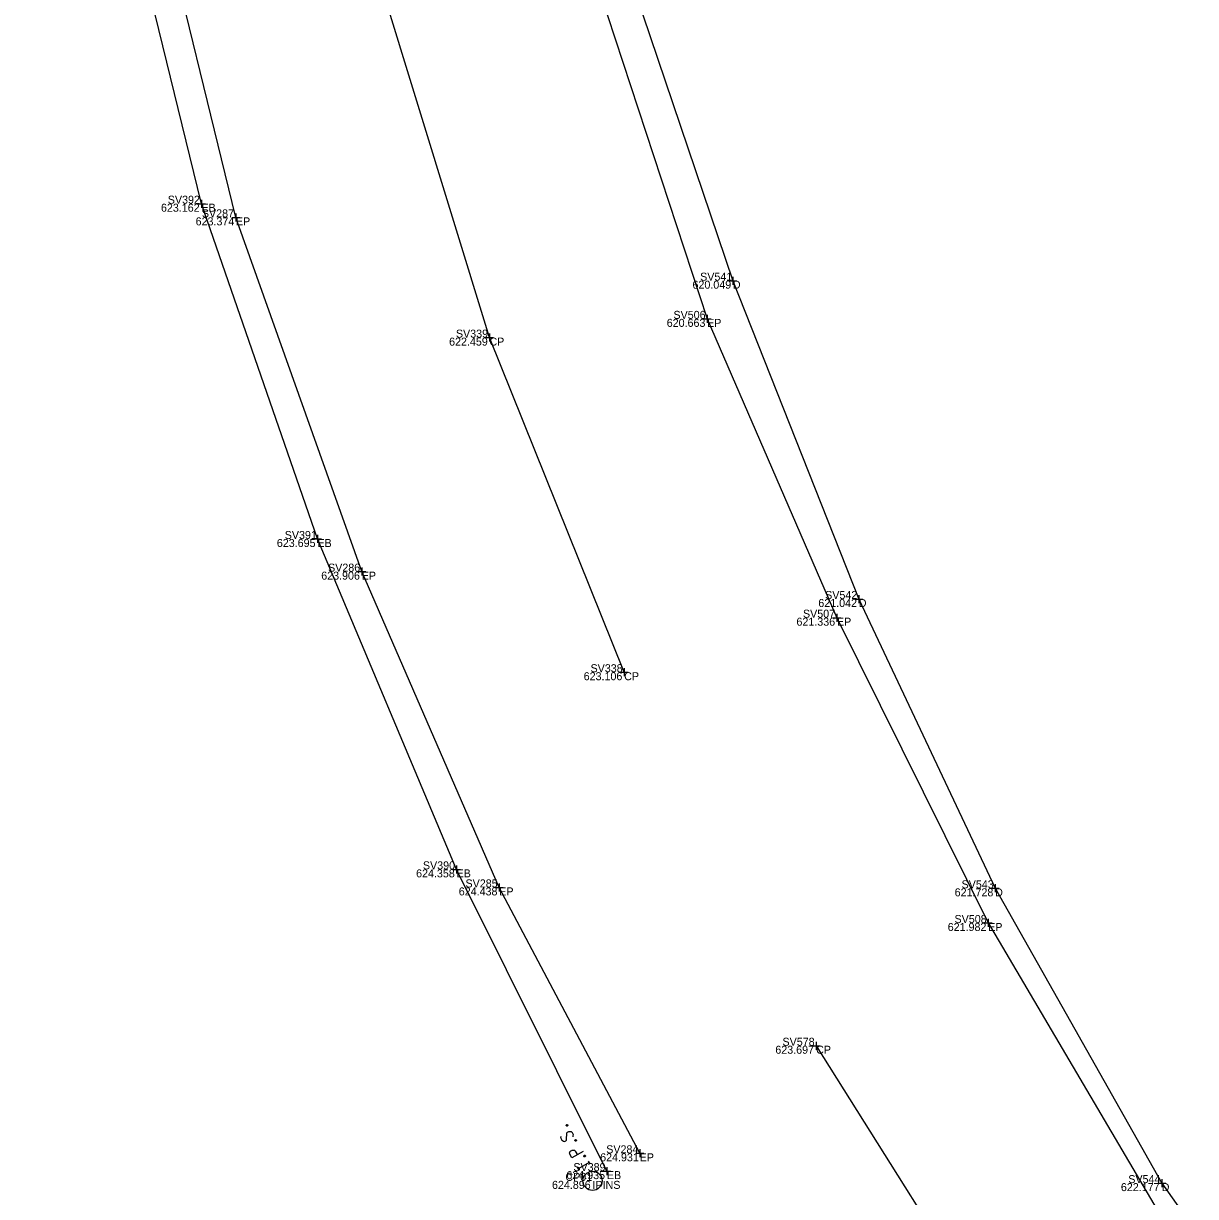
# Model space of a CAD drawing. Extents: x -2 to 1979875, y -2 to 232027.
# Drawn here: x 1978733.8 to 1978807.1, y 230654.1 to 230727.4 of the extents above; entities that cross this region are included whole.
import ezdxf

# ---------------------------------------------------------------- set-up
doc = ezdxf.new("R2010")
doc.units = 0
for name, color, linetype in [('_CIVIL_CONSTRUCTION', 7, 'Continuous'), ('DR_X_Ditch', 7, 'Continuous'), ('GE_X_Alignment', 7, 'Continuous'), ('GE_X_Alignment_1000_Curve_Data', 7, 'Continuous'), ('GE_X_Alignment_1000_Stations', 7, 'Continuous'), ('GE_X_Alignment_100_Curve_Data', 7, 'Continuous'), ('GE_X_Alignment_100_Stations', 7, 'Continuous'), ('RW_X_CL', 7, 'Continuous'), ('SC_Scratch1', 7, 'Continuous')]:
    doc.layers.add(name, color=color, linetype=linetype)

msp = doc.modelspace()

# ---------------------------------------------------------------- linework, layer by layer
at = {"layer": 'DR_X_Ditch'}
msp.add_lwpolyline([(1978771.125, 230732.191), (1978778.159, 230711.366), (1978786.031, 230691.476), (1978794.555, 230673.399), (1978804.965, 230654.98), (1978815.554, 230639.968), (1978828.294, 230624.497), (1978844.456, 230606.581), (1978859.572, 230591.097), (1978875.392, 230576.708), (1978886.516, 230567.847)], dxfattribs=at)
at = {"layer": 'GE_X_Alignment_1000_Curve_Data'}
for points in [[(1978771.368, 230686.901), (1978762.945, 230707.808), (1978756.184, 230729.845), (1978751.49, 230752.309), (1978748.994, 230772.916), (1978748.08, 230796.049), (1978747.937, 230796.247), (1978748.471, 230819.071), (1978749.254, 230839.296), (1978750.532, 230861.092), (1978751.977, 230883.907), (1978753.538, 230907.259), (1978755.272, 230931.005), (1978756.708, 230952.708), (1978758.182, 230974.871), (1978759.598, 230998.872), (1978761.121, 231023.464)], [(1978783.367, 230663.563), (1978795.266, 230644.644), (1978809.509, 230625.195), (1978825.084, 230606.888), (1978841.992, 230589.345), (1978859.09, 230573.66), (1978877.78, 230558.412), (1978896.865, 230543.975), (1978915.415, 230530.323), (1978933.509, 230517.252), (1978955.215, 230501.713), (1978975.371, 230487.136), (1978995.733, 230472.378), (1979015.234, 230458.051), (1979036.078, 230442.897)]]:
    msp.add_lwpolyline(points, dxfattribs=at)
at = {"layer": 'GE_X_Alignment_1000_Stations'}
for points in [[(1978772.336, 230656.843), (1978763.559, 230673.456), (1978754.964, 230693.186), (1978747.098, 230715.323), (1978742.189, 230735.369), (1978738.656, 230754.308), (1978736.533, 230775.816), (1978735.988, 230798.596), (1978736.151, 230819.454), (1978737.13, 230840.16), (1978738.357, 230863.144), (1978739.649, 230887.098), (1978741.331, 230908.702), (1978742.827, 230930.869), (1978744.275, 230952.773), (1978745.794, 230976.041), (1978747.11, 230998.611), (1978748.464, 231019.612), (1978749.988, 231043.472)], [(1978769.847, 230729.415), (1978776.553, 230708.98), (1978784.668, 230690.309), (1978794.119, 230671.233), (1978804.682, 230653.303), (1978817.78, 230635.658), (1978827.58, 230622.57), (1978841.659, 230607.55), (1978855.429, 230592.978), (1978873.114, 230576.871), (1978893.268, 230560.833), (1978915.513, 230544.403), (1978933.587, 230531.196), (1978953.659, 230517.09), (1978973.227, 230503.602), (1978990.133, 230491.392), (1979010.591, 230476.223), (1979030.079, 230461.641), (1979044.057, 230451.677)]]:
    msp.add_lwpolyline(points, dxfattribs=at)
at = {"layer": 'GE_X_Alignment_100_Curve_Data'}
for p, q in [((1978744.942, 230716.425), (1978744.942, 230715.925)), ((1978744.692, 230716.175), (1978745.192, 230716.175)), ((1978744.942, 230716.175), (1978744.942, 230716.175)), ((1978747.098, 230715.573), (1978747.098, 230715.073)), ((1978746.848, 230715.323), (1978747.348, 230715.323)), ((1978747.098, 230715.323), (1978747.098, 230715.323)), ((1978777.909, 230711.366), (1978778.409, 230711.366)), ((1978778.159, 230711.616), (1978778.159, 230711.116)), ((1978778.159, 230711.366), (1978778.159, 230711.366)), ((1978776.303, 230708.98), (1978776.803, 230708.98)), ((1978776.553, 230709.23), (1978776.553, 230708.73)), ((1978776.553, 230708.98), (1978776.553, 230708.98)), ((1978762.695, 230707.808), (1978763.195, 230707.808)), ((1978762.945, 230708.058), (1978762.945, 230707.558)), ((1978762.945, 230707.808), (1978762.945, 230707.808)), ((1978751.943, 230695.227), (1978752.443, 230695.227)), ((1978752.193, 230695.477), (1978752.193, 230694.977)), ((1978752.193, 230695.227), (1978752.193, 230695.227)), ((1978754.714, 230693.186), (1978755.214, 230693.186)), ((1978754.964, 230693.436), (1978754.964, 230692.936)), ((1978754.964, 230693.186), (1978754.964, 230693.186)), ((1978785.781, 230691.476), (1978786.281, 230691.476)), ((1978786.031, 230691.726), (1978786.031, 230691.226)), ((1978786.031, 230691.476), (1978786.031, 230691.476)), ((1978784.418, 230690.309), (1978784.918, 230690.309)), ((1978784.668, 230690.559), (1978784.668, 230690.059)), ((1978784.668, 230690.309), (1978784.668, 230690.309)), ((1978771.368, 230687.151), (1978771.368, 230686.651)), ((1978771.118, 230686.901), (1978771.618, 230686.901)), ((1978771.368, 230686.901), (1978771.368, 230686.901)), ((1978760.641, 230674.584), (1978761.141, 230674.584)), ((1978760.891, 230674.834), (1978760.891, 230674.334)), ((1978760.891, 230674.584), (1978760.891, 230674.584)), ((1978763.309, 230673.456), (1978763.809, 230673.456)), ((1978763.559, 230673.706), (1978763.559, 230673.206)), ((1978763.559, 230673.456), (1978763.559, 230673.456)), ((1978794.305, 230673.399), (1978794.805, 230673.399)), ((1978794.555, 230673.649), (1978794.555, 230673.149)), ((1978794.555, 230673.399), (1978794.555, 230673.399)), ((1978793.869, 230671.233), (1978794.369, 230671.233)), ((1978794.119, 230671.483), (1978794.119, 230670.983)), ((1978794.119, 230671.233), (1978794.119, 230671.233)), ((1978783.117, 230663.563), (1978783.617, 230663.563)), ((1978783.367, 230663.813), (1978783.367, 230663.313)), ((1978783.367, 230663.563), (1978783.367, 230663.563)), ((1978772.336, 230657.093), (1978772.336, 230656.593)), ((1978772.086, 230656.843), (1978772.586, 230656.843)), ((1978772.336, 230656.843), (1978772.336, 230656.843)), ((1978770.038, 230655.73), (1978770.538, 230655.73)), ((1978770.288, 230655.98), (1978770.288, 230655.48)), ((1978770.288, 230655.73), (1978770.288, 230655.73)), ((1978804.715, 230654.98), (1978805.215, 230654.98)), ((1978804.965, 230655.23), (1978804.965, 230654.73)), ((1978804.965, 230654.98), (1978804.965, 230654.98))]:
    msp.add_line(p, q, dxfattribs=at)
at = {"layer": 'RW_X_CL'}
for points in [[(1978767.754, 230658.556), (1978767.74, 230658.58), (1978767.743, 230658.601), (1978767.756, 230658.627), (1978767.784, 230658.643), (1978767.814, 230658.641), (1978767.833, 230658.633), (1978767.847, 230658.609), (1978767.844, 230658.589), (1978767.83, 230658.562), (1978767.803, 230658.546), (1978767.773, 230658.548), (1978767.754, 230658.556)], [(1978767.405, 230657.886), (1978767.399, 230657.87), (1978767.397, 230657.849), (1978767.405, 230657.797), (1978767.424, 230657.738), (1978767.446, 230657.7), (1978767.454, 230657.685), (1978767.507, 230657.633), (1978767.569, 230657.599), (1978767.632, 230657.59), (1978767.682, 230657.606), (1978767.714, 230657.625), (1978767.753, 230657.659), (1978767.769, 230657.72), (1978767.782, 230658.077), (1978767.79, 230658.113), (1978767.806, 230658.135), (1978767.834, 230658.163), (1978767.866, 230658.182), (1978767.902, 230658.196), (1978767.927, 230658.204), (1978767.959, 230658.21), (1978767.987, 230658.213), (1978768.009, 230658.213), (1978768.033, 230658.208), (1978768.052, 230658.2), (1978768.074, 230658.187), (1978768.088, 230658.176), (1978768.118, 230658.136), (1978768.157, 230658.069), (1978768.17, 230658.02), (1978768.168, 230657.936), (1978768.157, 230657.879)], [(1978768.297, 230657.61), (1978768.283, 230657.633), (1978768.286, 230657.654), (1978768.299, 230657.681), (1978768.327, 230657.697), (1978768.357, 230657.695), (1978768.376, 230657.687), (1978768.39, 230657.663), (1978768.387, 230657.642), (1978768.373, 230657.615), (1978768.346, 230657.6), (1978768.316, 230657.601), (1978768.297, 230657.61)], [(1978768.798, 230656.951), (1978768.105, 230656.552), (1978767.973, 230656.782), (1978767.965, 230656.809), (1978767.956, 230656.849), (1978767.959, 230656.869), (1978767.962, 230656.89), (1978767.978, 230656.925), (1978767.997, 230656.955), (1978768.035, 230656.989), (1978768.101, 230657.027), (1978768.126, 230657.035), (1978768.164, 230657.044), (1978768.213, 230657.047), (1978768.24, 230657.037), (1978768.26, 230657.029), (1978768.284, 230657.011), (1978768.312, 230656.976), (1978768.443, 230656.747)], [(1978769.188, 230656.272), (1978768.494, 230655.874)], [(1978768.856, 230656.634), (1978768.843, 230656.658), (1978768.845, 230656.679), (1978768.859, 230656.706), (1978768.886, 230656.721), (1978768.916, 230656.72), (1978768.936, 230656.712), (1978768.949, 230656.688), (1978768.947, 230656.667), (1978768.933, 230656.64), (1978768.906, 230656.624), (1978768.876, 230656.626), (1978768.856, 230656.634)], [(1978769.232, 230656.195), (1978769.144, 230656.348)], [(1978768.538, 230655.797), (1978768.45, 230655.95)]]:
    msp.add_lwpolyline(points, dxfattribs=at)
msp.add_circle((1978769.388, 230655.121), 0.6, dxfattribs=at)
at = {"layer": 'SC_Scratch1'}
msp.add_lwpolyline([(1978770.288, 230655.73), (1978760.891, 230674.584), (1978752.193, 230695.227), (1978744.942, 230716.175), (1978738.905, 230740.874), (1978735.553, 230763.886), (1978733.918, 230787.98), (1978733.819, 230809.219), (1978734.805, 230833.453), (1978736.148, 230858.007), (1978737.85, 230882.597), (1978739.105, 230905.756), (1978740.693, 230929.953), (1978742.419, 230953.633), (1978743.494, 230976.312), (1978745.216, 230999.029), (1978746.767, 231023.392)], dxfattribs=at)

# ---------------------------------------------------------------- texts
at = {"layer": '_CIVIL_CONSTRUCTION'}
for s, p in [('623.162', (1978742.414, 230715.675)), ('623.374', (1978744.582, 230714.823)), ('620.049', (1978775.638, 230710.866)), ('620.663', (1978774.028, 230708.48)), ('622.459', (1978760.424, 230707.308)), ('623.695', (1978749.658, 230694.727)), ('623.906', (1978752.432, 230692.686)), ('621.042', (1978783.503, 230690.976)), ('621.336', (1978782.136, 230689.809)), ('623.106', (1978768.836, 230686.401)), ('624.358', (1978758.361, 230674.084)), ('624.438', (1978761.029, 230672.956)), ('621.728', (1978792.025, 230672.899)), ('621.982', (1978791.591, 230670.733)), ('623.697', (1978780.816, 230663.063)), ('624.931', (1978769.866, 230656.343)), ('624.935', (1978767.753, 230655.23)), ('624.896', (1978766.856, 230654.621)), ('624.896', (1978766.856, 230654.621)), ('622.177', (1978802.414, 230654.48))]:
    msp.add_text(s, height=0.5, dxfattribs=at).set_placement(p)
at = {"layer": 'GE_X_Alignment'}
for s, p in [('SV392', (1978742.841, 230716.175)), ('SV287', (1978744.973, 230715.323)), ('SV541', (1978776.116, 230711.366)), ('SV506', (1978774.448, 230708.98)), ('SV339', (1978760.851, 230707.808)), ('SV391', (1978750.15, 230695.227)), ('SV286', (1978752.859, 230693.186)), ('SV542', (1978783.93, 230691.476)), ('SV507', (1978782.543, 230690.309)), ('SV338', (1978769.265, 230686.901)), ('SV390', (1978758.787, 230674.584)), ('SV285', (1978761.45, 230673.456)), ('SV543', (1978792.457, 230673.399)), ('SV508', (1978792.016, 230671.233)), ('SV578', (1978781.264, 230663.563)), ('SV284', (1978770.247, 230656.843)), ('SV389', (1978768.194, 230655.73)), ('CP01', (1978767.694, 230655.121)), ('CP01', (1978767.694, 230655.121)), ('SV544', (1978802.876, 230654.98))]:
    msp.add_text(s, height=0.5, dxfattribs=at).set_placement(p)
at = {"layer": 'GE_X_Alignment_100_Stations'}
for s, p in [('EB', (1978744.942, 230715.675)), ('EP', (1978747.098, 230714.823)), ('D', (1978778.159, 230710.866)), ('EP', (1978776.553, 230708.48)), ('CP', (1978762.945, 230707.308)), ('EB', (1978752.193, 230694.727)), ('EP', (1978754.964, 230692.686)), ('D', (1978786.031, 230690.976)), ('EP', (1978784.668, 230689.809)), ('CP', (1978771.368, 230686.401)), ('EB', (1978760.891, 230674.084)), ('EP', (1978763.559, 230672.956)), ('D', (1978794.555, 230672.899)), ('EP', (1978794.119, 230670.733)), ('CP', (1978783.367, 230663.063)), ('EP', (1978772.336, 230656.343)), ('EB', (1978770.288, 230655.23)), ('IPINS', (1978769.388, 230654.621)), ('IPINS', (1978769.388, 230654.621)), ('D', (1978804.965, 230654.48))]:
    msp.add_text(s, height=0.5, dxfattribs=at).set_placement(p)

doc.saveas('drawing.dxf')
